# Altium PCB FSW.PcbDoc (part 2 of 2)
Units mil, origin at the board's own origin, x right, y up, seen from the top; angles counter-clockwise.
Board outline 4340.74 x 2765.94 mil, 4 copper layers (Top Layer, Layer 1, Layer 2, Bottom Layer), stack 63.43 mil thick; 152 components, 72 nets, 476 pads, 391 vias.
Unrouted connection lines stored in the file: 225.
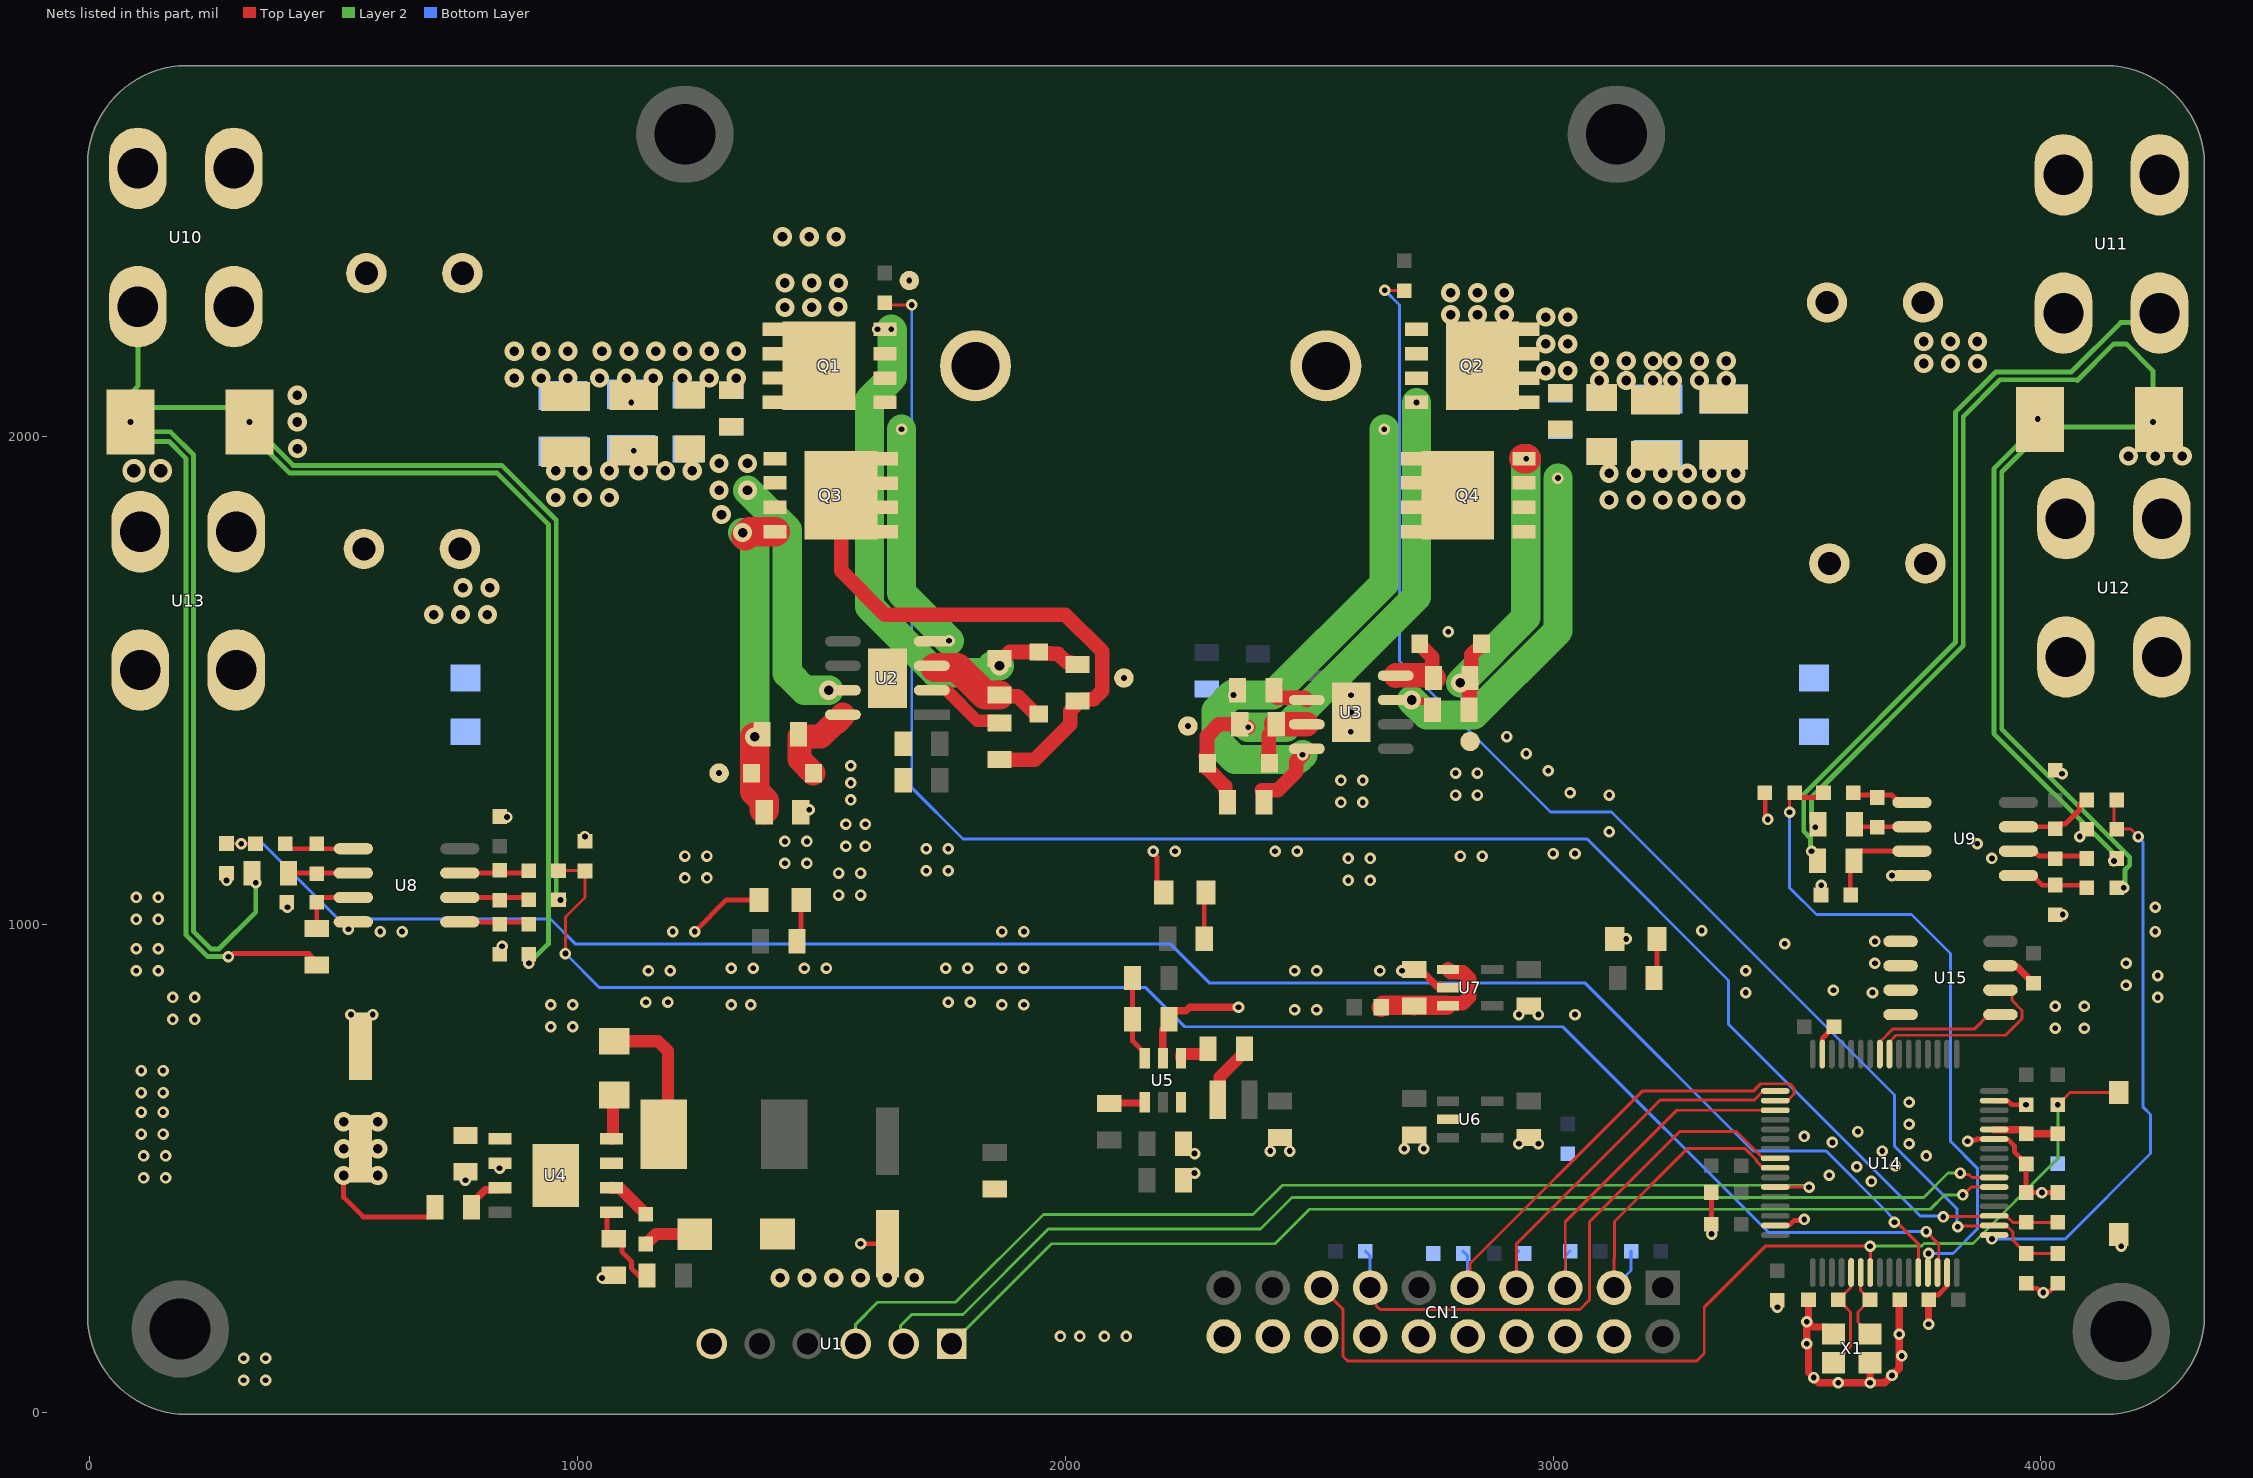
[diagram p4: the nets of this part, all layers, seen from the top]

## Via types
v1: diameter 23.62, hole 11.81, Top Layer to Bottom Layer, tented both sides, 276 vias
v2: diameter 39.37, hole 19.68, Top Layer to Bottom Layer, tented both sides, 113 vias
v3: diameter 47.24, hole 27.56, Top Layer to Bottom Layer, tented both sides, 2 vias

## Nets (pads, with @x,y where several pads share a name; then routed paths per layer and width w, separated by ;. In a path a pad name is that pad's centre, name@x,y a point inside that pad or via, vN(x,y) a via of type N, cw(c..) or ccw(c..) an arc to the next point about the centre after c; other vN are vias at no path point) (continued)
GND: C1.1 C2.1 C3.1 C4.1 C6.1 C7.1 C8.2 C11.1 C12.1 C13.1 C14.1 C15.1 C16.2 C17.1 C18.1 C19.2 C20.1 C21.1 C22.1 C23.1 C26.1 C27.1 C28.2 C30.1 C31.2 C32.1 C33.1 C35.2 C36.1 C37.1 C38.1 C39.1 C46.1 C47.2 C48.1 C49.1 C50.2 C51.1 C52.1 C53.2 C54.2 C55.1 C56.1 C57.1 C58.1 C59.1 C60.1 C61.1 C62.1 C63.1 C64.1 C65.1 C66.1 C67.1 C71.1 CN1.4 CN1.6 CN1.8 CN1.10 CN1.12 CN1.14 CN1.16 CN1.18 CN1.20 D5.1 LED1.1 LED3.1 LED4.1 pad.2 Q3.1 Q3.2 Q3.3 Q4.1 Q4.2 Q4.3 R7.1 R8.2 R11.1 R12.1 R13.1 R14.1 R18.1 R19.2 R24.1 R29.1 R33.1 R34.1 R39.1 R41.1 R44.1 R48.2 R56.1 R58.1 SW1.1 U1.6 U2.7 U2.9 U3.7 U3.9 U4.2 U5.2 U6.2 U7.2 U8.4 U9.4 U14.15 U14.27 U14.31 U14.47 U14.63 U15.1 U15.2 U15.3 U15.4 U15.7 X1.2 X1.4 | length 6202.9
  Top Layer w10: v1(1240,985) 1305,1050 LED1.1@1371.69,1050 ; v1(1580,345) 1616.4,345 1622.7,338.7 1622.7,287.3 v2(1635,275) ; v1(2180,1150) 2180,1146.31 2187.71,1138.6 2187.71,1074.68 LED3.1@2202.4,1060 ; R24.1@3324.41,445 3325,444.41 v1(3325,365) ; C51.1@3434.41,1270 3435,1269.41 3435,1223.69 3440,1218.69 v1(3440,1215) ; U14.63@3455.59,382.52 3455.94,382.86 3484.18,382.86 3493.71,392.39 3512.39,392.39 v1(3515,395) ; U14.47@3552.05,733.94 3552.4,734.29 3552.4,766.22 C57.1@3576.18,790 ; C58.1@3770,230 3780,240 3789.74,240 3807.6,257.86 3807.6,285.71 U14.15@3807.95,286.06 ; v1(3850,555) 3852.61,557.61 3862.24,557.61 3862.58,557.95 3867.05,557.95 3868.77,559.67 U14.27@3904.41,559.67 3904.76,559.33 3932.61,559.33 3945.86,546.08 3945.86,533.55 C1.1@3970,509.41 C55.1@3970,450 R58.1@4035,450 ; U14.31@3904.41,638.41 3904.76,638.07 3932.61,638.07 3940.67,630 v1(3970,630) ; R56.1@3970,263.82 3980,253.82 3992.5,253.82 4001.31,245 v1(4005,245) 4007.61,247.61 4018.79,247.61 C46.1@4035,263.82 ; v1(4080,1180) 4080,1180.59 C52.1@4094.41,1195
  Top Layer w15: U5.2@2200,725.3 2200,785.1 2212.4,797.5 R19.2@2212.4,805 2212.4,812.5 2222.4,822.5 2247.5,822.5 2255,830 v1(2355,830) ; U3.7@2677.37,1460 v2(2710,1460) 2712.5,1457.5 2742.6,1457.5 2752.6,1447.5 R12.1@2752.6,1440 ; C38.1@2715,907.4 2725,897.4 2737.6,897.4 2762.85,872.15 2772.85,872.15 U7.2@2770,875 ; U7.2@2773.88,872.15 2776.03,870 U7.2@2784.6,870 ; C6.1@3523.82,230 3523.82,191.15 3520,187.33 v1(3520,185) ; X1.2@3575,160 3560.85,174.15 3533.18,174.15 3522.33,185 v1(3520,185) ; X1.4@3649.8,100.94 3650,100.74 v1(3650,60) ; C8.2@3711.18,230 3710,228.82 3710,90 3680,60 v1(3650,60) ; v1(3770,180) C58.1@3770,230 ; U15.7@3917.37,915 3918.93,913.44 3950.97,913.44 C4.1@3985,879.41 ; v1(3520,185) 3520,143.82 3523.82,140 3523.82,81.18 3545,60 v1(3585,60) v1(3650,60)
  Layer 2 w10: v1(327.1,2030) 329.71,2027.39 329.71,2005.29 410,1925 835,1925 940,1820 940,960 v1(900,920) ; v1(3993.87,2036.13) 3991.26,2033.52 3991.26,2021.26 3904,1934 3904,1391 4148.54,1146.46 4148.54,1131.46 v1(4150,1130)
  Layer 2 w30: v2(1295,1840) v2@1296.79,1841.79
  Layer 2 w60: v2(1348.31,1890) 1430,1808.31 1430,1515 1465.15,1479.85 1514.85,1479.85 v2(1515,1480) ; v2(2710,1460) 2741,1429 2837.34,1429 3010,1601.66 v1(3010,1915)
  other v1: 315,65 360,65 3534.41,70.59 3695,75 315,110 360,110 3715,115 3520,140 1990,155 2030,155 2080,155 2125,155 3710,159.41 3460,215 1050,275 4165,340 4002.5,450 3652.78,472.78 770,475 110,480 155,480 3566.24,485.27 2265,490 840,500 3622.78,502.78 3701.24,505.27 110,525 155,525 3765,525 2265,530 2420,535 2460,535 3675,535 2695,540 2735,540 2930,550 2970,550 3730,550 3572.78,552.78 3515,565 105,570 150,570 3625,575 3730,590 105,615 150,615 3730,635 105,655 150,655 105,700 150,700 4029.67,786.8 4089.67,786.8 945,790 990,790 170,805 215,805 535,815 580,815 2930,815 2970,815 3045,815 2470,825 2515,825 4029.67,831.8 4089.67,831.8 945,835 990,835 1315,835 1355,835 1870,835 1915,835 1140,840 1185,840 1760,840 1805,840 170,850 215,850 4240,850 3395,860 3655,860 3575,865 4175,875 4240,895 95,905 140,905 1145,905 1190,905 2470,905 2515,905 2645,905 2690,905 3395,905 1315,910 1360,910 1465,910 1510,910 1755,910 1800,910 1870,910 1915,910 3660,920 4175,920 95,950 140,950 845,955 3475,960 3660,965 3150,970 595,985 640,985 1195,985 1870,985 1915,985 4235,985 3305,987.19 530,990 95,1010 140,1010 4045,1020 405,1035 4235,1035 95,1055 140,1055 1535,1060 1580,1060 3550,1080 280,1090 2580,1090 2625,1090 1220,1095 1265,1095 3695,1100 1535,1105 1580,1105 1715,1110 1760,1110 1425,1125 1470,1125 2580,1135 2625,1135 3900,1135 1220,1140 1265,1140 2810,1140 2855,1140 3000,1145 3045,1145 2225,1150 2430,1150 2475,1150 1715,1155 1760,1155 1550,1160 1590,1160 3870,1165 1425,1170 1470,1170 1015,1180 3115,1190 1550,1205 1590,1205 855,1220 1475,1235 2565,1250 2610,1250 1560,1255 2800,1265 2845,1265 3115,1265 3035,1270 1560,1290 2565,1295 2610,1295 4043.63,1308.63 1290,1310 2800,1310 2845,1310 2990,1315 1560,1325 2945,1350 2905,1385 2585,1395 2251.24,1406.61 2586.18,1435 2585.48,1469.52 2120,1505 2785,1600 1115,1970.83 1680,2320
  other v2: 1415,275 1470,275 1525,275 1580,275 1690,275 3115,1870 3170,1870 3225,1870 3275,1870 3325,1870 3375,1870 955,1875 1010,1875 1065,1875 1290,1890 3115,1925 3170,1925 3225,1925 3275,1925 3325,1925 3375,1925 955,1930 1010,1930 1065,1930 1125,1930 1180,1930 1235,1930 1290,1945 1348.31,1945 425.51,1975.51 425,2030 425,2085 3760,2150 3815,2150 3870,2150 3760,2195 3815,2195 3870,2195
HGATE1: D1.1 Q1.4 R3.2 R9.2 | length 1070.2
  Top Layer w30: R3.2@1872.5,1544.8 1886.1,1558.4 1941.1,1558.4 1941.1,1557.3 1942.3,1556.1 1968.9,1556.1 1970,1555 1984.9,1555 2002.5,1537.4 R9.2@2010,1537.4
  Layer 2 w60: v1(1643.19,2220) 1645.31,2217.88 1645.31,2122.39 1598.19,2075.27 1598.19,1651.81 1734.33,1515.67 1835.67,1515.67 1850,1530 v2(1865,1530)
  other v1: 1615,2220
HGATE2: D2.1 Q2.4 R4.2 R10.1 | length 1081.2
  Top Layer w30: 2327.6,1275 2327.6,1282.5 2290.5,1319.59 2290.5,1342.7 2288.2,1345 2290.5,1347.3 2290.5,1385.5 2315,1410 R4.2@2357.6,1410 2357.6,1406.5 2360.1,1404 v1(2375,1404)
  Layer 2 w60: v1(2375,1404) 2452.34,1404 2720,1671.66 v1(2720,2070)
I_IN: C49.2 R32.2 U14.14 | length 3363.8
  Top Layer w6: R32.2@960.59,1110 1014.41,1110 C49.2@1015,1109.41 1015,1055 975,1015 v1(975,940) ; v1(3765,370) 3790.81,344.19 3790.81,316.38 3789.38,314.95 3789.38,287.17 U14.14@3788.27,286.06
  Bottom Layer w6: v1(975,940) 1045,870 2165,870 2245,790 3020,790 3441.62,368.38 3723.31,368.38 3724.93,370 v1(3765,370)
I_OUT: C52.2 R42.2 U14.17 | length 1173.5
  Top Layer w6: R42.2@4150.59,1255 4150.59,1195 4185,1195 v1(4200,1180)
  Bottom Layer w6: v1(3900,355) 4050,355 4225,530 4225,610 4210,625 4210,1167.67 4200,1177.67 v1(4200,1180)
LGATE1: D3.1 Q3.4 R5.2 R11.2 | length 650.8
  Top Layer w60: v2@1344.38,1796.24 1353.14,1805 Q3.4@1405,1805 ; v2(1363.21,1384.21) 1363.21,1272.15 1382.6,1252.75 R11.2@1382.6,1235
  Layer 2 w60: v2(1338.21,1803.21) 1363.21,1778.21 v2(1363.21,1384.21)
LGATE2: D4.1 Q4.4 R6.2 R12.2 | length 666.6
  Top Layer w30: R12.2@2827.4,1440 2828.6,1441.2 2828.6,1503.8 R6.2@2829.8,1505 2832.3,1507.5 2832.3,1552.3 2853.4,1573.4 D4.1@2853.4,1575
  Top Layer w60: Q4.4@2940,1955 2940.2,1954.8 v1(2945,1954.8)
  Layer 2 w60: v2(2810,1495) 2944,1629 2944,1953.8 v1(2945,1954.8)
LX: C34.1 L3.1 U5.6 | length 127.8
  Top Layer w25: L3.1@2312.32,640 2316.55,644.25 2316.55,686.65 2367.4,737.5 C34.1@2367.4,745
NetC24_2: C24.2 U2.2 | length 134
  Top Layer w25: U2.2@1758.24,1478.17 1819.01,1417.4 1860,1417.4 C24.2@1865,1412.4
NetC25_2: C25.2 U3.2 | length 90.7
  Top Layer w30: C25.2@2427.4,1490 2429.9,1487.5 2429.9,1469.33 2434.9,1464.33 2490.67,1464.33 U3.2@2495,1460
NetC29_1: C29.1 U4.6 | length 93
  Top Layer w25: U4.6@1069.5,460 1070.2,459.3 1086.29,459.3 C29.1@1140,405.59
NetC34_2: C34.2 U5.1 | length 70.8
  Top Layer w25: U5.1@2237.4,725.3 2237.4,731.85 2239.45,733.9 2287.6,733.9 2292.6,738.9 C34.2@2292.6,745
NetC38_2: C38.2 L4.2 U7.1 U7.3 | length 277.6
  Top Layer w30: U7.3@2784.6,832.6 2789.95,837.95 2814.7,837.95 2828.4,851.65 2828.4,888.35 2814.7,902.05 2789.95,902.05 U7.1@2784.6,907.4
  Top Layer w40: L4.2@2647.5,830 2651.87,834.37 2713.23,834.37 C38.2@2715,832.6 2716.75,834.35 U7.3@2781.8,834.35
NetD1_2: D1.2 R3.1 U2.3 | length 246.3
  Top Layer w30: R3.1@1865,1470 1867.5,1467.5 1902.5,1467.5 1938.4,1431.6 D1.2@1940,1431.6
  Top Layer w60: U2.3@1733.07,1526.67 1778.33,1526.67 1835,1470 R3.1@1865,1470
NetD2_2: D2.2 R4.1 U3.3 | length 134.8
  Top Layer w30: D2.2@2415,1345 2417.3,1347.3 2417.3,1387.4 2432.4,1402.5 R4.1@2432.4,1410
  Top Layer w50: R4.1@2432.4,1410 U3.3@2495,1410
NetD3_2: D3.2 R5.1 U2.8 | length 195.9
  Top Layer w50: D3.2@1483.4,1310 1454.8,1338.6 1454.8,1385 1498.82,1385 1529.49,1415.67 1531.93,1415.67 1543.82,1427.56 U2.8@1543.82,1430
NetD4_2: D4.2 R6.1 U3.8 | length 162
  Top Layer w30: D4.2@2726.6,1575 2726.6,1573.4 2752.5,1547.5 2752.5,1507.5 R6.1@2755,1505
  Top Layer w50: U3.8@2677.37,1510 2678.05,1510.69 2749.31,1510.69 R6.1@2755,1505
NetLED1_2: LED1.2 R59.1 | length 88.5
  Top Layer w10: R59.1@1449.8,965 1458.31,973.5 LED1.2@1458.31,1050
NetLED3_2: LED3.2 R61.1 | length 91.7
  Top Layer w10: R61.1@2284.8,970 2284.8,1055.78 LED3.2@2289.02,1060
NetLED4_2: LED4.2 R62.1 | length 82.4
  Top Layer w10: R62.1@3207.4,890 3213.31,895.91 LED4.2@3213.31,970
NetR15_2: R15.2 U4.3 | length 79.1
  Top Layer w15: R15.2@782.4,420 782.4,427.5 810.6,455.7 836.2,455.7 U4.3@840.5,460
NetR16_1: R16.1 U4.8 | length 93.5
  Top Layer w25: U4.8@1069.5,560 1071.55,560 1072.25,560.7 1072.25,647.25 R16.1@1075,650
NetR17_1: R17.1 R18.2 U4.5 | length 198.3
  Top Layer w10: U4.5@1069.5,410 1066.8,410 1060,403.2 1060,355.23 1078.15,355.23 1090.65,342.73 1090.65,328.58 1110.25,308.99 1110.25,294.85 1125.1,280 1137.6,267.5 R17.1@1137.6,260
NetR19_1: R19.1 R20.2 U5.3 | length 175.1
  Top Layer w10: R20.2@2137.6,890 2137.6,760.95 2162.6,735.95 U5.3@2162.6,725.3
NetR21_2: R21.2 U5.4 | length 73.6
  Top Layer w15: R21.2@2090,632.4 2091.2,633.6 2161.4,633.6 U5.4@2162.6,634.8
NetR25_1: R25.1 R27.1 U8.1 | length 143.6
  Top Layer w10: R27.1@400.59,1165 410.59,1155 U8.1@540,1155
NetR25_2: R25.2 R26.2 U8.2 | length 139.4
  Top Layer w10: R26.2@400.59,1105 U8.2@540,1105
NetR28_2: R28.2 R29.2 U8.3 | length 139.1
  Top Layer w10: R28.2@465,985 R29.2@465,1045 475,1055 U8.3@540,1055
NetR30_1: R30.1 R32.1 U8.7 | length 143.2
  Top Layer w10: U8.7@758.3,1105 840,1105 894.41,1105 R32.1@899.41,1110
NetR30_2: R30.2 R31.2 U8.6 | length 143.2
  Top Layer w10: U8.6@758.3,1055 894.41,1055 R31.2@899.41,1050
NetR33_2: R33.2 R34.2 U8.5 | length 143.8
  Top Layer w10: U8.5@758.3,1005 840,1005 895,1005 R33.2@900,1000
NetR35_1: R35.1 R37.1 U9.1 | length 128.6
  Top Layer w10: R37.1@3615.59,1270 3620.59,1265 3695,1265 3710,1250 U9.1@3735.9,1250
NetR35_2: R35.2 R36.2 U9.2 | length 126.8
  Top Layer w10: R36.2@3611.18,1205 3616.18,1200 U9.2@3735.9,1200
NetR38_2: R38.2 R39.2 U9.3 | length 186.7
  Top Layer w10: 3609.41,1075 3609.41,1128.82 R38.2@3610.59,1130 ; R38.2@3617.4,1130 3617.4,1137.5 3629.9,1150 U9.3@3735.9,1150
NetR40_1: R40.1 R42.1 U9.7 | length 167.8
  Top Layer w10: U9.7@3954.2,1200 4025.59,1200 R40.1@4030,1195.59 4040,1205.59 4050.59,1205.59 4079.41,1234.41 4079.41,1245 R42.1@4089.41,1255
NetR40_2: R40.2 R41.2 U9.6 | length 146.4
  Top Layer w10: U9.6@3954.2,1150 3986.44,1150 3996.44,1140 4089.41,1140 R41.2@4094.41,1135
NetR43_2: R43.2 R44.2 U9.5 | length 148.5
  Top Layer w10: U9.5@3954.2,1100 3982.9,1100 4002.9,1080 R43.2@4094.41,1080
NRST: CN1.15 R1.2 SW1.2 U14.7 | length 2155.7
  Top Layer w6: CN1.15@2525,255 2569.43,210.57 2569.43,114.08 2578.51,105 3295,105 3310,120 3310,215 3435,340 v1(3650,340) 3650.47,339.53 U14.7@3650.47,286.06 ; v1(4035,630) 4047,642 4060,655 SW1.2@4160,655
  Layer 2 w6: v1(3650,340) 3754.88,340 3760.7,345.81 3860.81,345.81 4035,520 v1(4035,630)
NTC0: C46.2 R55.1 R56.2 U14.18 | length 2755
  Top Layer w6: v1(2655,2300) 2694.41,2300 R55.1@2695,2299.41 ; v1(3830,380) 3831.4,381.4 3903.3,381.4 U14.18@3904.41,382.52 3929.42,382.52 3942.94,369 3942.94,352.06 3958,337 R56.2@3970,325 ; R56.2@3978.47,333.47 3986.94,325 C46.2@4035,325
  Bottom Layer w6: v1(2655,2300) 2685,2270 2685,1540 2995,1230 3120,1230 3700,650 3700,545 3828.62,416.38 3828.62,381.38 v1(3830,380)
NTC1: C55.2 R57.1 R58.2 U14.19 | length 3820.5
  Top Layer w6: R57.1@1630,2274.41 1634.41,2270 v1(1685,2270) ; v1(3800,400) 3801.1,401.1 3903.31,401.1 U14.19@3904.41,402.19 3929.43,402.19 3942.81,388.82 C55.2@3970,388.82 R58.2@4035,388.82
  Bottom Layer w6: v1(1685,2270) 1685,1280 1790,1175 3070,1175 3360,885 3360,795 3753.5,401.5 3798.5,401.5 v1(3800,400)
OSC_IN: C6.2 U14.5 X1.3 | length 221.9
  Top Layer w6: X1.3@3575,100.94 3576.97,100.94 3610,133.97 3610,205 3597,218 C6.2@3585,230 3609.99,254.99 3609.99,284.94 U14.5@3611.1,286.06
OSC_OUT: C8.1 U14.6 X1.1 | length 155.8
  Top Layer w6: U14.6@3630.79,286.06 3630.79,249.21 C8.1@3650,230 3625,205 3625,184.8 3629.18,180.62 3629.18,178.65 3647.83,160 X1.1@3649.8,160
PA13: CN1.7 R47.1 U14.49 | length 827.4
  Top Layer w6: CN1.7@2925,255 2925,345 3220,640 3412.47,640 3430.58,658.11 U14.49@3455.59,658.11
  Bottom Layer w6: CN1.7@2925,255 2925,325 R47.1@2930,330
PA14: CN1.9 R48.1 U14.50 | length 1007.9
  Top Layer w6: CN1.9@2825,255 2829.43,259.43 2829.43,304.45 3182.79,657.81 3410.6,657.81 3425.79,673.01 3485.39,673.01 3494.12,664.28 3494.12,651.93 3480.6,638.41 U14.50@3455.59,638.41
  Bottom Layer w6: R48.1@2815,330 2825,320 CN1.9@2825,255
PA15: CN1.5 R46.1 U14.51 | length 739.5
  Top Layer w6: CN1.5@3025,255 3025,390 3253.73,618.73 U14.51@3455.59,618.73
  Bottom Layer w6: CN1.5@3025,255 3025,320 R46.1@3035,330
PB3: CN1.13 R22.1 U14.56 | length 1210.5
  Top Layer w6: CN1.13@2625,255 2637.41,242.59 2637.41,217.59 2645,210 3055,210 3075,230 3075,390 3259.95,574.95 3375.94,574.95 3430.58,520.31 U14.56@3455.59,520.31
  Bottom Layer w6: R22.1@2615,330 2625,320 CN1.13@2625,255
PB4: CN1.3 R45.1 U14.57 | length 635.1
  Top Layer w6: CN1.3@3125,255 3125,315.57 3125.81,316.38 3125.81,390.81 3275,540 3393.91,540 3417.06,516.85 3417.06,514.13 3430.57,500.62 U14.57@3455.59,500.62
  Bottom Layer w6: CN1.3@3125,255 3160,290 R45.1@3160,330
PC8: U14.40 U15.6 | length 402.7
  Top Layer w6: U14.40@3689.84,733.94 3689.84,758.96 3703.36,772.47 3927.79,772.47 3961.79,806.48 3961.79,823.52 3940.89,844.42 3940.89,857.08 3932.97,865 U15.6@3917.37,865
PC9: U14.41 U15.5 | length 295.4
  Top Layer w6: U14.41@3670.16,733.94 3670.16,758.97 3696.19,785 3863.5,785 3893.5,815 U15.5@3917.37,815
PWR_EN: U1.3 U14.59 | length 2184.4
  Top Layer w6: U14.59@3455.59,461.26 3524.56,461.26 v1(3525,460.81)
  Layer 2 w6: U1.3@1570,140 1570,180 1615,225 1775,225 1955,405 2385,405 2445,465 3512.67,465 3513.49,464.18 3521.63,464.18 v1(3525,460.81)
RX: U1.2 U14.23 | length 2415.5
  Top Layer w6: v1(3835,490) 3838.37,486.63 3853.12,486.63 3858.81,480.93 U14.23@3904.41,480.93
  Layer 2 w6: U1.2@1668.43,140 1661.98,146.44 1661.98,176.98 1685,200 1790,200 1965,375 2400,375 2465,440 3760,440 3810,490 v1(3835,490)
SW1: C24.1 L1.1 Q1.1 Q1.2 Q1.3 Q3.5 Q3.6 Q3.7 Q3.8 Q3.9 R9.1 U2.4 | length 1597.8
  Top Layer w30: Q3.9@1540.4,1880 1540.4,1724.6 1630,1635 2000,1635 2075.28,1559.72 2075.28,1479.31 2057.71,1461.73 2050.43,1461.73 2048.79,1460.1 2032.58,1460.1 2010,1437.52 2010,1410 1937.6,1337.6 C24.1@1865,1337.6
  Layer 2 w60: v1(1664.19,2015) 1664.19,1679.15 v1(1761.67,1581.67)
SW2: C25.1 L1.2 Q2.1 Q2.2 Q2.3 Q4.5 Q4.6 Q4.7 Q4.8 Q4.9 R10.2 U3.4 | length 1153.2
  Top Layer w30: 2402.4,1275 2435,1275 2473.11,1313.11 2473.11,1334.14 v1(2486.5,1347.53)
  Layer 2 w60: v1@2343.06,1471.94 2309,1437.87 2309,1376.66 2347.66,1338 2476.97,1338 v1(2486.5,1347.53) ; v1(2345,1470) 2425,1470 2654,1699 v1(2654,2015)
TX: U1.1 U14.22 | length 2271.5
  Top Layer w6: v1(3840,445) 3841.16,445 3857.42,461.26 U14.22@3904.41,461.26
  Layer 2 w6: U1.1@1766.85,140 1766.85,141.49 1793.86,168.49 1795.35,168.49 1971.85,345 2430,345 2500.81,415.81 3773.43,415.81 3802.62,445 v1(3840,445)
V_IN: C48.2 R27.2 U14.12 | length 3900.7
  Top Layer w6: C48.2@280,1165.59 338.82,1165.59 R27.2@339.41,1165 ; v1(3700,389.19) 3704.77,389.19 3748.9,345.06 U14.12@3748.9,286.06
  Bottom Layer w6: v1(310,1165) 355,1165 509.19,1010.81 944.19,1010.81 995,960 2215,960 2295,880 3065,880 3410,535 3560,535 3688.78,406.22 3689.02,406.22 3689.02,404.94 3700,393.96 v1(3700,389.19)
V_OUT: C51.2 R37.2 U14.13 | length 1358.1
  Top Layer w6: v1(3485,1230) 3485,1258 3487,1260 3500.59,1260 3500.59,1265 C51.2@3495.59,1270 ; C51.2@3505.59,1260 C51.2@3507.59,1258
  Top Layer w10: C51.2@3500.59,1260 3505.59,1260 R37.2@3550,1260
  Bottom Layer w6: v1(3485,1230) 3485,1075 3540,1020 3735,1020 3815,940 3815,555 3870,500 3870,375 3820,325 v1(3770,325)
VIN+: C20.2 C21.2 C22.2 C23.2 C27.2 C28.1 C53.1 C54.1 C64.2 C65.2 C66.2 C67.2 Q1.5 Q1.6 Q1.7 Q1.8 Q1.9 R7.2 R15.1 R28.1 U4.1 U4.9 U10.1 U10.2 U10.3 U10.4 | length 1962.4
  Top Layer w10: U10.3@285,2560 U10.3@295,2550 ; 293.87,940 448.82,940 R28.1@465,923.82 ; v2(520,485) 520,440 560,400 695.1,400 707.6,412.5 R15.1@707.6,420
  Layer 2 w10: U10.1@98.15,2266.54 98.15,2103.15 60.19,2065.19 60.19,2019.81 90,1990 162.37,1990 196.69,1955.68 196.69,978.31 241.32,933.68 v1(283.87,933.68)
  other v1: 1110,2070
  other v2: 590,485 520,540 590,540 520,595 590,595 705,1635 760,1635 815,1635 765,1690 820,1690 870,2120 925,2120 980,2120 1045,2120 1100,2120 1155,2120 1215,2120 1270,2120 1325,2120 870,2175 925,2175 980,2175 1050,2175 1105,2175 1160,2175 1215,2175 1270,2175 1325,2175 1425,2265 1480,2265 1534.11,2266.33 1425,2315 1480,2315 1535,2315 1420,2410 1475,2410 1530,2410
VIN-: R8.1 R26.1 R31.1 U13.1 U13.2 U13.3 U13.4 | length 3153.9
  Layer 2 w10: v1(340,1085) 340,1025 264.68,949.68 247.94,949.68 212.69,984.94 212.69,1962.31 165,2010 103,2010 v1(83,2030) 113,2060 335,2060 350,2045 350,2007.63 416.63,1941 844,1941 956,1829 956,1062.69 965,1053.69 v1(965,1050)
  other v3: 90,1930 145,1930
VOUT+: C15.2 C16.1 C17.2 C18.2 C19.1 C26.2 C60.2 C61.2 C62.2 C63.2 Q2.5 Q2.6 Q2.7 Q2.8 Q2.9 R13.2 R38.1 U11.1 U11.2 U11.3 U11.4 | length 1538.1
  Layer 2 w10: v1(3530,1150) 3527.93,1152.07 3527.93,1176.81 3514,1190.74 3514,1266.74 3825,1577.74 3825,2050 3907.5,2132.5 4062.5,2132.5 4163.66,2233.66 4223.82,2233.66 U11.2@4243.42,2253.27
  other v2: 3095,2115 3150,2115 3205,2115 3245,2115 3300,2115 3355,2115 2985,2135 3030,2135 3095,2155 3150,2155 3205,2155 3245,2155 3300,2155 3355,2155 2985,2190 3030,2190 2985,2245 3030,2245 2790,2250 2845,2250 2900,2250 2790,2295 2845,2295 2900,2295
VOUT-: R14.2 R36.1 R43.1 U12.1 U12.2 U12.3 U12.4 | length 2872.5
  Layer 2 w10: v1(3537.81,1199.19) 3537.81,1202.88 3530,1210.69 3530,1260 3841,1571 3841,2041 3916.5,2116.5 4073.5,2116.5 4075,2115 4150,2190 4175,2190 4230,2135 v1(4230,2030) 4227.33,2030 4217.33,2020 4012.63,2020 3920,1927.37 3920,1400 4182.59,1137.41 4182.59,1121.39 4172.61,1111.4 4172.61,1077.61 v1(4170,1075)
  other v2: 4180,1960 4235,1960 4290,1960
VREF+: C1.2 R23.2 U14.28 | length 134.2
  Top Layer w15: U14.28@3904.41,579.37 3904.69,579.08 3972.72,579.08 3981.21,570.59 R23.2@4035,570.59
VS: C29.2 D5.2 L2.1 R16.2 U4.7 | length 400.8
  Top Layer w25: R16.2@1075,760.23 1164.77,760.23 1185,740 1185,578.1 L2.1@1176.9,570 ; C29.2@1140,344.41 1160.59,365 1240,365 D5.2@1240.4,364.6
pads on no net: *.1 CN1.11 CN1.17 CN1.19 U4.4 U6.4 U7.4 U14.2 U14.3 U14.4 U14.8 U14.9 U14.10 U14.11 U14.20 U14.21 U14.24 U14.25 U14.26 U14.30 U14.33 U14.34 U14.35 U14.36 U14.37 U14.38 U14.39 U14.46 U14.52 U14.53 U14.54 U14.55 U14.60 U14.62

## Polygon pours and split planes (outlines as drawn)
GND on Top Layer "GND_L01_P051" (solid, pour order 51): 945,875 985,915 985,1000 1040,1055 1040,1170 1110,1240 1330,1240 1375,1195 1525,1195 1525,1085 1520,1080 1370,1080 1330,985 1375,940 1375,745 1325,695 1220,695 1220,705 1200,725 1200,775 1175,800 950,800 920,830 920,860
GND on Top Layer "GND_L01_P054" (solid, pour order 54): 3245,995 3255,1005 3770,1005 3805,1040 3880,1040 3890,1030 3890,940 3895,935 3955,935 3965,925 3965,905 3945,885 3880,885 3855,860 3855,810 3840,795 3625,795 3605,775 3570,775 3505,840 3265,840 3245,855
GND on Top Layer "GND_L01_P040" (solid, pour order 40): 2220,445 2218.9,446.1 2218.9,581 2246,581 2250,585 2255,580 2385,580 2400,595 2403.9,591.1 2731.25,591.1 2755.8,615.65 2814.35,615.65 2820,610 2820,590 2805,575 2760,575 2755,570 2755,365 2685,295 2330,295 2330,290 2240,200 2240,50 2215,25 1870,25 1805,90 1805,470 1830,495 1855,495 1950,400 2175,400
+5V on Top Layer "+5V_L01_P036" (solid, pour order 36): 2355,695 2370,710 2495,710 2545,760 2545,855 2565,875 2620,875 2630,865 2630,705 2650,685 2800,685 2820,665 2820,620 2815,615 2755,615 2730,590 2430,590 2425,595 2400,595 2385,580 2360,580 2355,585 2355,595 2355,650
VS on Top Layer "VS_L01_P032" (solid, pour order 32): 1055,535 1095,535 1115,555 1115,645 1140,670 1300,670 1330,640 1330,330 1315,315 1180,315 1160,335 1160,415 1105,470 1100,470 1090,480 1050,480 1040,490 1040,535
GND on Top Layer "GND_L01_P017" (solid, pour order 17): 2900,1925 2910,1935 2965,1935 2975,1945 2975,2025 3000,2050 3035,2050 3075,2010 3387.5,2010 3410,1987.5 3410,1595 3530,1475 3655,1475 3715,1535 3715,2365 3760,2410 3930,2410 3985,2355 3985,2180 4035,2130 4100,2130 4120,2110 4120,1960 4090,1930 4000,1930 3960,1890 3960,1395 3865,1300 3070,1300 2900,1470 2900,1680
VOUT+ on Top Layer "VOUT+_L01_P016" (solid, pour order 16): 4305,2640 4210,2735 2780,2735 2755,2710 2755,1995 2765,1985 2925,1985 2990,2050 3035,2050 3101.67,2010 3387.5,2010 3410,1995 3410,1595 3530,1475 3655,1475 3715,1535 3715,2365 3760,2410 3930,2410 3985,2355 3985,2180 4035,2130 4280,2130 4305,2155
SW2 on Top Layer "SW2_L01_P014" (solid, pour order 14): 2900,1965 2890,1975 2775,1975 2755,1995 2755,2235 2745,2245 2600,2245 2425,2245 2400,2220 2400,1665 2445,1620 2885,1620 2894.68,1629.68
GND on Top Layer "GND_L01_P004" (solid, pour order 4): 195,2085 240,2130 315,2130 365,2180 365,2355 420,2410 590,2410 610,2390 610,1560 695,1475 820,1475 885,1540 885,2005 900,2020 1255,2020 1285,2050 1350,2050 1430,1970 1445,1955 1445,1550 1320,1425 1155,1260 490,1260 360,1390 360,1870 305,1925 225,1925 195,1950 195,1975
VIN+ on Top Layer "VIN+_L01_P002" (solid, pour order 2): 15,2610 140,2735 1570,2735 1595,2710 1595,1995 1585,1985 1415,1985 1350,2050 1285,2050 1260,2030 1250,2025 905,2025 885,2005 885,1540 820,1475 695,1475 610,1560 610,2390 590,2410 420,2410 365,2355 365,2180 315,2130 55,2130 15,2170 15,2410
GND on Top Layer "GND_L01_P057" (solid, pour order 57): 3965,850 3965,890 3985,910 4055,910 4195,770 4195,705 4175,685 4080,685 4040,725 3945,725 3927.79,742.21 3927.79,772.47 3970,814.68 3970,845
GND on Top Layer "GND_L01_P056" (solid, pour order 56): 4080,1050 4265,1050 4330,985 4330,390 4210,270 4105,270 4060,315 4060,470 4085,495 4155,495 4235,575 4235,790 4055,970 4055,1025
GND on Top Layer "GND_L01_P055" (solid, pour order 55): 3495,610 3505,620 3675,620 3735,680 3820,680 3840,660 3835,655 3835,450 3750,365 3520,365 3493.71,391.29 3493.71,392.39
+3.3V on Top Layer "+3.3V_L01_P053" (solid, pour order 53): 2850,660 2975,785 3050,785 3100,835 3100,915 3115,930 3155,930 3175,910 3175,835 3270,835 3470,835 3515,790 3510,785 3510,725 3460,675 3150,675 3045,570 2980,570 2950,600 2940,590 2860,590 2850,600
GND on Top Layer "GND_L01_P044" (solid, pour order 44): 95,870 100,875 980,875 1020,835 1020,670 985,635 500,635 465,600 465,480 565,380 925,380 1020,285 1020,70 980,30 200,30 30,200 30,800 75,845
GND on Top Layer "GND_L01_P050" (solid, pour order 50): 1540,1240 1510,1210 1510,950 1560,900 1710,900 1740,870 1740,795 1770,765 1865,765 1945,845 1945,1020 1710,1240
GND on Top Layer "GND_L01_P049" (solid, pour order 49): 2525,1320 2530,1325 2530,1500 2565,1535 2630,1535 2645,1520 2640,1515 2640,1345 2645,1340 2740,1340 2720,1320
GND on Top Layer "GND_L01_P047" (solid, pour order 47): 2525,1320 2720,1320 2795,1395 2930,1395 3045,1280 3380,1280 3420,1240 3420,1210 3445,1185 3505,1185 3515,1175 3515,1080 3475,1040 3060,1040 2960,940 2395,940 2355,980 2355,1150
GND on Top Layer "GND_L01_P045" (solid, pour order 45): 40,1220 230,1220 255,1195 255,860 195,800 30,800 30,1210
+12V on Top Layer "+12V_L01_P039" (solid, pour order 39): 1360,670 1570,880 1675,880 1700,855 1700,775 1735,740 1900,740 1955,685 1955,670
GND on Top Layer "GND_L01_P038" (solid, pour order 38): 1340,415 1350,425 1760,425 1770,415 1770,280 1720,230 1360,230 1340,250
GND on Top Layer "GND_L01_P042" (solid, pour order 42): 1585,1580 1600,1595 1680,1595 1695,1580 1695,1245 1670,1220 1560,1220 1540,1240 1540,1340 1585,1385 1585,1420
LX on Top Layer "LX_L01_P034" (solid, pour order 34): 2220,665 2240,685 2335,685 2340,680 2340,595 2330,585 2230,585 2220,595
+12V on Top Layer "+12V_L01_P033" (solid, remove dead copper, pour order 33): 1330,640 1380,690 1945,690 2040,595 2170,595 2180,605 2180,660 2190,670 2210,670 2220,660 2220,445 2175,400 1950,400 1855,495 1805,495 1745,435 1360,435 1330,465
VIN+ on Top Layer "VIN+_L01_P030" (solid, pour order 30): 480,615 505,640 935,640 1000,575 1040,535 1035,530 1035,410 1015,390 905,390 875,420 875,520 860,535 795,535 790,530 780,520 680,520 600,440 590,430 515,430 465,480 465,595
VOUT- on Top Layer "VOUT-_L01_P018" (solid, pour order 18): 4125,2130 4295,2130 4325,2100 4325,1390 4290,1355 3980,1355 3960,1375 3960,1890 4000,1930 4090,1930 4120,1960 4120,2120
SW1 on Top Layer "SW1_L01_P012" (solid, pour order 12): 1450,1965 1460,1975 1575,1975 1595,1995 1595,2190 1605,2200 1705,2200 1750,2245 1925,2245 1950,2220 1950,1665 1905,1620 1465,1620 1455.32,1629.68
VIN- on Top Layer "VIN-_L01_P006" (solid, pour order 6): 15,2170 55,2130 227.01,2130 233.51,2123.51 195,2085 195,1955 225,1925 305,1925 360,1870 360,1390 450,1300 450,1260 420,1230 55,1230 15,1270 15,1655
GND on Bottom Layer "GND_L04_P041" (solid, pour order 41): 15,1200 1135,1200 1595,1660 1595,2515 1750,2670 2635,2670 2720,2585 2720,1675 3160,1235 4200,1235 4320,1115 4320,150 4185,15 145,15 15,145
GND on Bottom Layer "GND_L04_P020" (solid, pour order 20): 3955.75,2350 3905.75,2400 3725.75,2400 3705.75,2380 3705.75,1560 3610.75,1465 3500.75,1465 3435.75,1530 3435.75,1995 3415.75,2015 3065.75,2015 3040.75,2040 2970.75,2040 2875.75,1945 2875.75,1540 3000.75,1415 3165.75,1250 3825.75,1250 3960.75,1385 3960.75,1865 4010.75,1915 4090.75,1915 4125.75,1950 4125.75,2075 4090.75,2110 4080.75,2110 4065.75,2125 4003.25,2125 3955.75,2172.5
GND on Bottom Layer "GND_L04_P008" (solid, pour order 8): 365,2360 415,2410 595,2410 615,2390 615,1570 710,1475 820,1475 885,1540 885,2005 905,2025 1255,2025 1280,2050 1350,2050 1445,1955 1445,1550 1320,1425 1155,1260 495,1260 360,1395 360,1875 310,1925 230,1925 195,1960 195,2085 230,2120 240,2120 255,2135 317.5,2135 365,2182.5
VOUT- on Bottom Layer "VOUT-_L04_P021" (solid, pour order 21): 4295,2145 4280,2130 4075,2130 4067.5,2122.5 4075,2115 4085,2115 4120,2080 4120,1955 4085,1920 4005,1920 3955,1870 3955,1390 3820,1255 3820,1220 3845,1195 4255,1195 4300,1240 4300,2135
VIN+ on Bottom Layer "VIN+_L04_P001" (solid, pour order 1): 15,2475 15,2610 140,2735 1355,2735 1570,2735 1595,2710 1595,2000 1580,1985 1415,1985 1350,2050 1280,2050 1250,2020 1245,2025 905,2025 885,2005 885,1540 820,1475 710,1475 615,1570 615,2390 595,2410 415,2410 365,2360 365,2180 360,2180 315,2135 35,2135 20,2150
VIN- on Bottom Layer "VIN-_L04_P009" (solid, pour order 9): 20,2150 35,2135 240,2135 247.5,2127.5 240,2120 230,2120 195,2085 195,1960 230,1925 310,1925 360,1875 360,1395 495,1260 495,1225 470,1200 60,1200 15,1245 15,2140
VOUT+ on Bottom Layer "VOUT+_L04_P019" (solid, pour order 19): 4305,2470 4305,2605 4180,2730 2965,2730 2750,2730 2725,2705 2725,1995 2740,1980 2905,1980 2970,2045 3040,2045 3070,2015 3075,2020 3415,2020 3435,2000 3435,1535 3500,1470 3610,1470 3705,1565 3705,2385 3725,2405 3905,2405 3955,2355 3955,2175 3960,2175 4005,2130 4285,2130 4300,2145
GND on Layer 1 "GND_L02_P027" (solid, pour order 27): 196.27,-4.98 cw(c200,200) -4.98,196.27 -5.01,196.85 -5.01,2559.06 -4.98,2559.64 cw(c200,2555.91) 196.27,2760.89 196.85,2760.92 4133.86,2760.92 4134.44,2760.89 cw(c4130.71,2555.91) 4335.69,2559.64 4335.72,2559.06 4335.72,196.85 4335.69,196.27 cw(c4130.71,200) 4134.44,-4.98 4133.86,-5.01
VIN+ on Layer 2 "VIN+_L03_P029" (solid, pour order 29): 447.48,1860 875,1860 915,1820 915,490 750,325 445,325 305,465 310,470 310,1734.27

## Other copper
Layer 1:
  pour cut-out: 311.54,2039.44 317.1,2045 337.1,2045 342.1,2040 342.1,2020 337.1,2015 317.1,2015 311.54,2020.56
  pour cut-out: 3979.44,2044.44 3985,2050 4005,2050 4010,2045 4010,2025 4005,2020 3985,2020 3979.44,2025.56
  pour cut-out: 1702.5,2210 1707.5,2215 1707.5,2345 1777.5,2345 1782.5,2350 1782.5,2720 2567.5,2720 2572.5,2715 2567.5,2710 2567.5,2350 2642.5,2350 2647.5,2345 2647.5,1950 2577.5,1950 2572.5,1945 2572.5,1580 1792.5,1580 1787.5,1575 1782.5,1580 1782.5,1945 1712.5,1945 1702.5,1955 1702.5,1985
  pour cut-out: 2705,1485 2715,1485 2735,1465 2735,1450 2720,1435 2705,1435 2685,1455 2685,1465
  pour cut-out: 1490,1490 1505,1505 1530,1505 1540,1495 1540,1470 1525,1455 1505,1455 1490,1470
  pour cut-out: 4134.44,1139.44 4140,1145 4160,1145 4165,1140 4165,1120 4160,1115 4140,1115 4134.44,1120.56
  pour cut-out: 885,935 910,935 915,930 915,906.67 905,900 890,900 880,910 880,930
Bottom Layer:
  pour cut-out: 4135,1140 4140,1145 4160,1145 4165,1140 4165,1120 4160,1115 4140,1115 4135,1120
  pour cut-out: 3980,2045 3985,2050 4005,2050 4010,2045 4010,2025 4005,2020 3985,2020 3980,2025 3980,2040
  pour cut-out: 2685,1465 2705,1485 2715,1485 2735,1465 2735,1450 2720,1435 2705,1435 2685,1455
  pour cut-out: 1490,1490 1505,1505 1530,1505 1540,1495 1540,1470 1525,1455 1505,1455 1490,1470 1490,1480
  pour cut-out: 310,2040 315,2045 340,2045 345,2040 345,2020 340,2015 315,2015 310,2020 310,2025
  pour cut-out: 885,930 890,935 910,935 915,930 915,910 910,905 890,905 885,910
  pour cut-out: 1780,2345 1710,2345 1710,1945 1785,1945 1785,1590 1795,1580 2570,1580 2570,1940 2580,1950 2650,1950 2650,2340 2640,2350 2570,2350 2570,2715 2565,2720 1780,2720

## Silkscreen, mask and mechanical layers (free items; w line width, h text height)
Top Overlay:
  text "SWCLK" at 2730,400 h30
  text "SWDIO" at 2895,400 h30
Top Solder:
  region: 4060,2725 3425,2725 3230,2530 3205,2505 2875,2505 2780,2410 2780,2260 2810,2230 3255,2230 3260,2235 3360,2235 3425,2300 3425,2435 3555,2565 3775,2565 3805,2565 3940,2430 4085,2430 4140,2485 4140,2645
  region: 3755,2060 3760,2075 3920,2075 3945,2050 3945,1420 3860,1335 3135,1335 2940,1530 2940,1820 2970,1850 3220,1850 3285,1785 3285,1610 3430,1465 3505,1465 3745,1465 3755,1475 3755,2040
  region: 390,2105 560,2105 585,2080 585,1500 655,1430 910,1430 1115,1635 1115,1835 1170,1890 1355,1890 1385,1860 1385,1570 1100,1285 660,1285 525,1285 395,1415 395,1715
  region: 290,2725 925,2725 1120,2530 1145,2505 1475,2505 1570,2410 1570,2260 1540,2230 1095,2230 1090,2235 990,2235 925,2300 925,2435 795,2565 575,2565 545,2565 410,2430 265,2430 210,2485 210,2645
Bottom Solder:
  region: 3965,2125 3795,2125 3770,2100 3770,1520 3700,1450 3445,1450 3240,1655 3240,1855 3185,1910 3000,1910 2970,1880 2970,1590 3255,1305 3695,1305 3830,1305 3960,1435 3960,1735
  region: 300,2730 935,2730 1130,2535 1155,2510 1485,2510 1580,2415 1580,2265 1550,2235 1105,2235 1100,2240 1000,2240 935,2305 935,2440 805,2570 585,2570 555,2570 420,2435 275,2435 220,2490 220,2650
  region: 4050,2730 3415,2730 3220,2535 3195,2510 2865,2510 2770,2415 2770,2265 2800,2235 3245,2235 3250,2240 3350,2240 3415,2305 3415,2440 3545,2570 3765,2570 3795,2570 3930,2435 4075,2435 4130,2490 4130,2650
  region: 385,2125 555,2125 580,2100 580,1520 650,1450 905,1450 1110,1655 1110,1855 1165,1910 1350,1910 1380,1880 1380,1590 1095,1305 655,1305 520,1305 390,1435 390,1735
Mechanical 1:
  lines w10: 0,196.85 0,2559.06 ; 0,200 ccw(c200,200) 200,0 ; 0,2555.91 cw(c200,2555.91) 200,2755.91 ; 196.85,0 4133.86,0 ; 196.85,2755.91 4133.86,2755.91 ; 4130.71,0 ccw(c4130.71,200) 4330.71,200 ; 4130.71,2755.91 cw(c4130.71,2555.91) 4330.71,2555.91 ; 4330.71,196.85 4330.71,2559.06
